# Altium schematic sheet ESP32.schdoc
size 267 x 210 mm
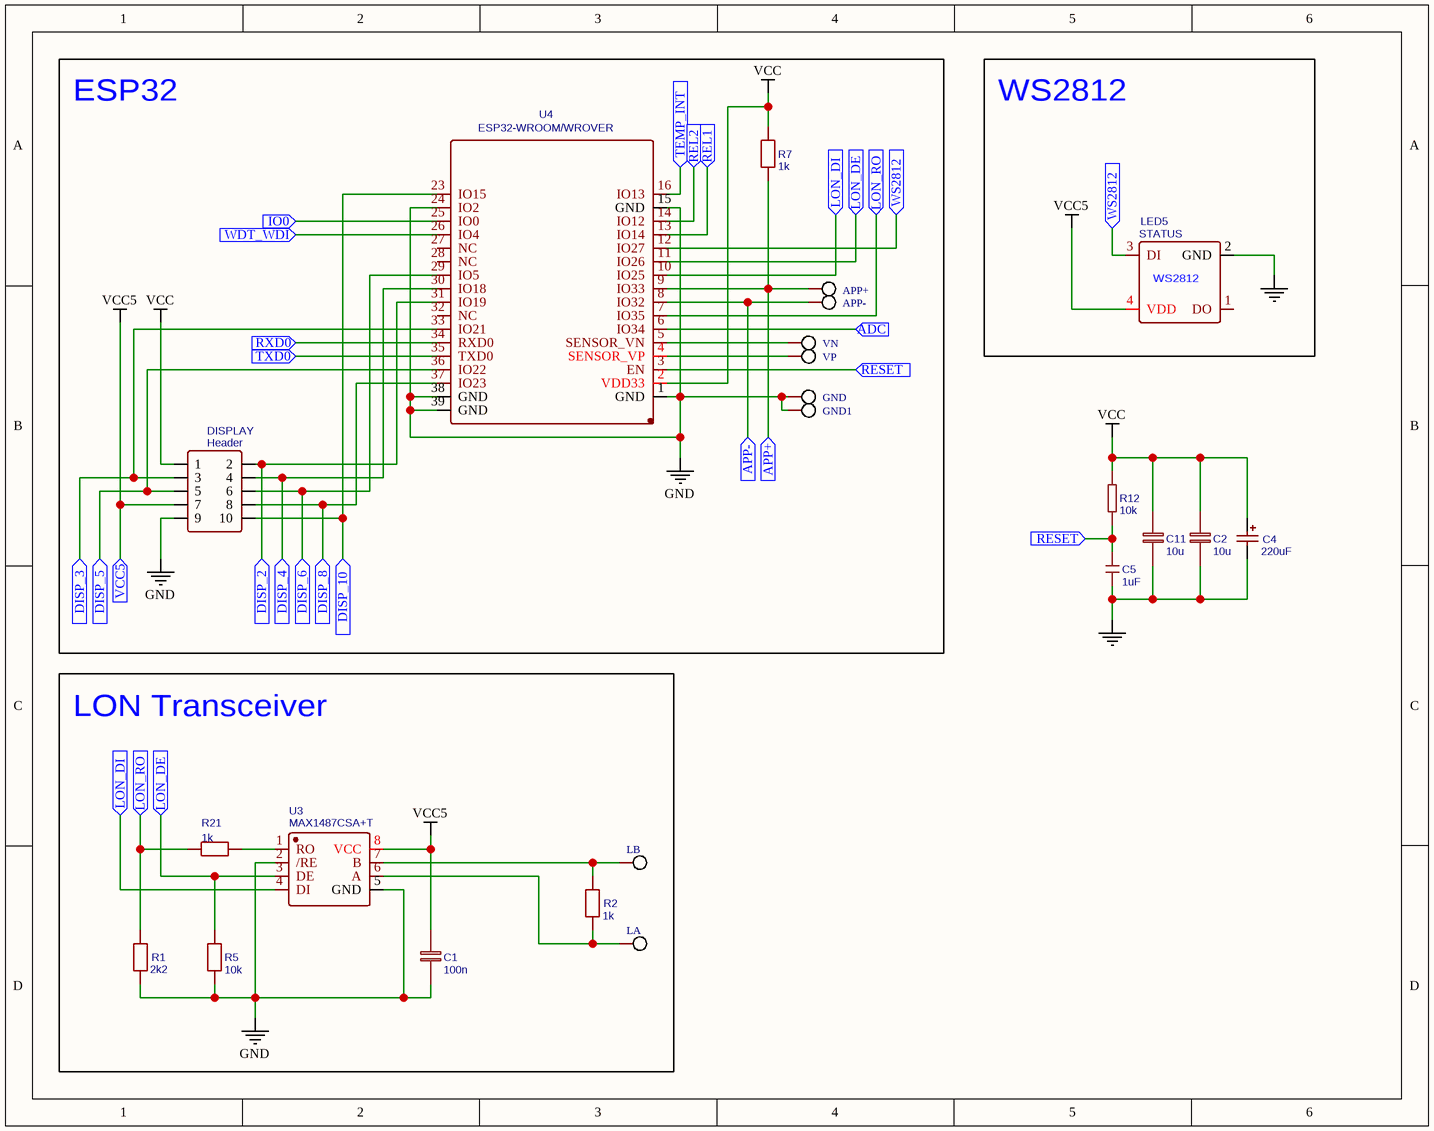
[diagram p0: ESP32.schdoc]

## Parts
APP+  Pad  [PAD]  (value not drawn)
APP-  Pad  [PAD]  (value not drawn)
C1  100n  [0603]
C2  10u  [0603]
C4  220uF  [CASE-B_3528]
C5  1uF  [0603]
C11  10u  [0603]
DISPLAY  Header  [HDR-5X2/2.54]
GND  Pad  [ROUND_PAD]  (value not drawn)
GND1  Pad  [ROUND_PAD]  (value not drawn)
LA  Pad  [PAD]  (value not drawn)
LB  Pad  [PAD]  (value not drawn)
LED5  STATUS  [LED_WS2812-2020_FL]
R1  2k2  [0603]
R2  1k  [0603]
R5  10k  [0603]
R7  1k  [0603]
R12  10k  [0603]
R21  1k  [0603]
U3  MAX1487CSA+T  [SOIC-8_150MIL]
U4  ESP32-WROOM/WROVER  [ESP32-WROOM-32U]
VN  Pad  [ROUND_PAD]  (value not drawn)
VP  Pad  [ROUND_PAD]  (value not drawn)

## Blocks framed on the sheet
ESP32: APP+ APP- DISPLAY GND GND1 R7 U4 VN VP
WS2812: LED5
LON Transceiver: C1 LA LB R1 R2 R5 R21 U3

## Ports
ADC (in), APP+ (in), APP- (in), DISP_2 (in), DISP_3 (in), DISP_4 (in), DISP_5 (in), DISP_6 (in), DISP_8 (in), DISP_10 (in), IO0 (in), LON_DE (in), LON_DI (in), LON_RO (in), REL1 (in), REL2 (in), RESET (in), RXD0 (in), TEMP_INT (in), TXD0 (in), VCC5 (in), WDT_WDI (in), WS2812 (in)

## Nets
GND: C1.2 C2.2 C4.2 C5.1 C11.2 DISPLAY.9 GND.1 GND1.1 LED5.2(GND) R1.2 R5.1 U3.2(/RE) U3.5(GND) U4.1(GND) U4.15(GND) U4.24(IO2) U4.38(GND) U4.39(GND)
VCC: C2.1 C4.1 C11.1 DISPLAY.1 R7.2 R12.2 U4.2(VDD33)
VCC5: C1.1 DISPLAY.7 LED5.4(VDD) U3.8(VCC) ; port VCC5
ADC: U4.6(IO34) ; port ADC
APP+: APP+.1 R7.1 U4.9(IO33) ; port APP+
APP-: APP-.1 U4.8(IO32) ; port APP-
DISP_2: DISPLAY.2 U4.31(IO19) ; port DISP_2
DISP_3: DISPLAY.3 U4.33(IO21) ; port DISP_3
DISP_4: DISPLAY.4 U4.30(IO18) ; port DISP_4
DISP_5: DISPLAY.5 U4.36(IO22) ; port DISP_5
DISP_6: DISPLAY.6 U4.29(IO5) ; port DISP_6
DISP_8: DISPLAY.8 U4.37(IO23) ; port DISP_8
DISP_10: DISPLAY.10 U4.23(IO15) ; port DISP_10
IO0: U4.25(IO0) ; port IO0
LON_DE: R5.2 U3.3(DE) U4.11(IO26) ; port LON_DE
LON_DI: U3.4(DI) U4.10(IO25) ; port LON_DI
LON_RO: R1.1 R21.2 U4.7(IO35) ; port LON_RO
REL1: U4.13(IO14) ; port REL1
REL2: U4.14(IO12) ; port REL2
RESET: C5.2 R12.1 U4.3(EN) ; port RESET
RXD0: U4.34(RXD0) ; port RXD0
TEMP_INT: U4.16(IO13) ; port TEMP_INT
TXD0: U4.35(TXD0) ; port TXD0
WDT_WDI: U4.26(IO4) ; port WDT_WDI
WS2812: LED5.3(DI) U4.12(IO27) ; port WS2812
NetLA_1: LA.1 R2.1 U3.6(A)
NetLB_1: LB.1 R2.2 U3.7(B)
NetR21_1: R21.1 U3.1(RO)
NetU4_4: U4.4(SENSOR_VP) VP.1
NetU4_5: U4.5(SENSOR_VN) VN.1

Not connected (* = marked no-connect by the designer): LED5 1(DO); U4 27(NC) 28(NC) 32(NC)

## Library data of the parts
C1 = 100n: BOM_Manufacturer Part: GRM188B11E104KA01D; BOM_Manufacturer: MuRata; nameAlias: Value(F)
C2 C11 = 10u: BOM_Manufacturer Part: GRM188R61C106MA73D; BOM_Manufacturer: MuRata; nameAlias: Value(F)
C4 = 220uF: BOM_Manufacturer: KEMET; BOM_Manufacturer Part: T490B227M006ATE500; nameAlias: Capacitance; SMT Type: Extend
C5 = 1uF: BOM_Manufacturer Part: GRM188R61C105KA12D; BOM_Manufacturer: MuRata
DISPLAY = Header: BOM_Manufacturer Part: 2*5pHeaders  Pins 2.54mm
LED5 = STATUS: Contributor: TomTheDragon
R1 = 2k2: BOM_Manufacturer Part: TC0325B2201T5E; BOM_Manufacturer: UniOhm; nameAlias: Value(Ω)
R2 R21 = 1k: BOM_Manufacturer Part: 0603WAD1001T5E; BOM_Manufacturer: UniOhm; nameAlias: Value(Ω)
R5 = 10k: BOM_Manufacturer Part: RC0603JR-0710KL; BOM_Manufacturer: YAGEO; nameAlias: Value(Ω)
R7 = 1k: BOM_Manufacturer Part: 0603WAD1001T5E; BOM_Manufacturer: UniOhm; nameAlias: Value(Ω); Package Display: No
R12 = 10k: BOM_Manufacturer Part: RC0603JR-0710KL; BOM_Manufacturer: YAGEO; Contributor: DangerousPrototype
U3 = MAX1487CSA+T: BOM_Manufacturer: MAXIM; SMT Type: Extend
U4 = ESP32-WROOM/WROVER: BOM_Manufacturer: Espressif Systems; BOM_Manufacturer Part: ESP32-WROVER; Contributor: LCSC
